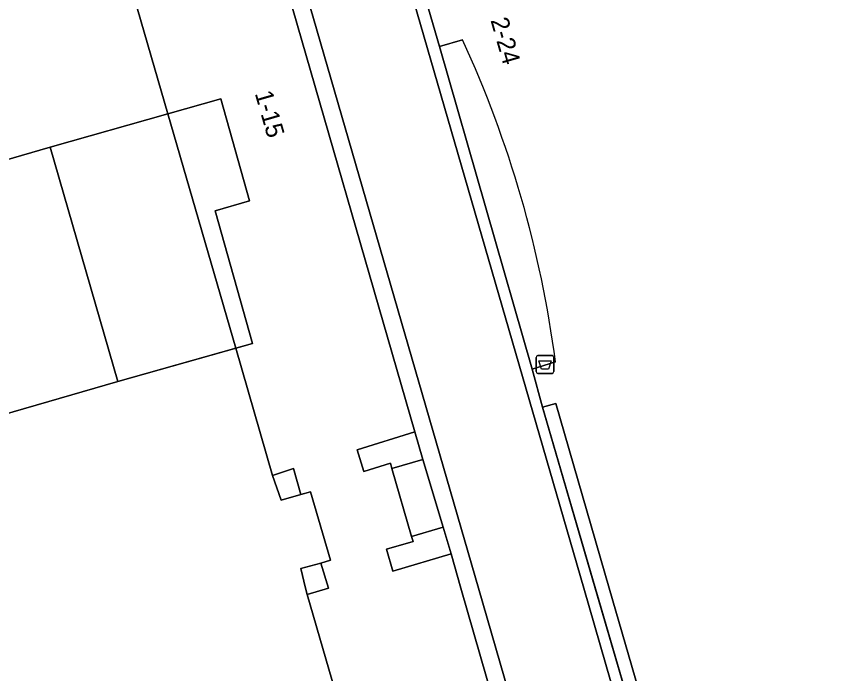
# Model space of a CAD drawing. Extents: x 160806 to 161707, y 383696 to 384148.
# Drawn here: x 161142.86 to 161189.04, y 383745.23 to 383782.03 of the extents above; entities that cross this region are included whole.
import ezdxf

# ---------------------------------------------------------------- set-up
doc = ezdxf.new("R2010")
doc.units = 0
for name, color, linetype in [('IMGEO_Afvalbak', 7, 'Continuous'), ('IMGEO_Muur', 7, 'Continuous'), ('IMGEO_Pand', 7, 'Continuous'), ('IMGEO_Pand_nummerreeks', 7, 'Continuous'), ('IMGEO_Pand_overbouw', 7, 'Continuous'), ('IMGEO_Parkeervlak_gesloten', 7, 'Continuous'), ('IMGEO_Parkeervlak_open', 7, 'Continuous'), ('IMGEO_Rijbaan_lokaal_gesloten', 7, 'Continuous'), ('IMGEO_Voetgangersgebied_open', 7, 'Continuous'), ('IMGEO_Voetpad_op_trap', 7, 'Continuous')]:
    doc.layers.add(name, color=color, linetype=linetype)

msp = doc.modelspace()

# ---------------------------------------------------------------- linework, layer by layer
at = {"layer": 'IMGEO_Afvalbak'}
for p, q in [((161172.084, 383763.034), (161172.874, 383763.034)), ((161172.874, 383763.034), (161172.084, 383763.034)), ((161171.984, 383762.134), (161171.984, 383762.934)), ((161171.984, 383762.934), (161171.984, 383762.134)), ((161172.974, 383762.934), (161172.974, 383762.134)), ((161172.974, 383762.134), (161172.974, 383762.934)), ((161172.874, 383762.034), (161172.084, 383762.034)), ((161172.084, 383762.034), (161172.874, 383762.034))]:
    msp.add_line(p, q, dxfattribs=at)
msp.add_lwpolyline([(161172.127, 383762.748), (161172.831, 383762.748), (161172.682, 383762.278), (161172.276, 383762.278), (161172.127, 383762.748)], dxfattribs=at)
for centre, start, end in [((161172.084, 383762.934), 90, 180), ((161172.084, 383762.934), 90, 180), ((161172.874, 383762.934), 0, 90), ((161172.874, 383762.934), 360, 90), ((161172.084, 383762.134), 180, 270), ((161172.084, 383762.134), 180, 270), ((161172.874, 383762.134), 270, 0), ((161172.874, 383762.134), 270, 0)]:
    msp.add_arc(centre, 0.1, start, end, dxfattribs=at)
at = {"layer": 'IMGEO_Muur'}
for points in [[(161165.635, 383757.209), (161165.188, 383758.759), (161161.944, 383757.756), (161162.319, 383756.541), (161163.812, 383757.001), (161163.896, 383756.713)], [(161157.692, 383754.928), (161158.801, 383755.259), (161158.381, 383756.705), (161157.212, 383756.317)], [(161165.005, 383752.909), (161165.089, 383752.622), (161163.592, 383752.184), (161163.95, 383750.966), (161167.213, 383751.923), (161166.779, 383753.429)], [(161159.142, 383749.659), (161160.337, 383750), (161159.91, 383751.416), (161158.79, 383751.101), (161159.059, 383750)]]:
    msp.add_lwpolyline(points, close=True, dxfattribs=at)
at = {"layer": 'IMGEO_Pand'}
for points in [[(161221.311, 383832.189), (161220.955, 383833.419), (161219.851, 383837.235), (161216.277, 383836.232), (161215.039, 383840.515), (161214.94, 383840.857), (161157.832, 383824.35), (161159.26, 383819.473), (161155.555, 383818.417), (161155.737, 383817.796), (161156.438, 383818.002), (161166.655, 383782.656), (161165.953, 383782.453), (161166.564, 383780.339), (161167.861, 383780.714)], [(161173.066, 383762.677), (161171.77, 383762.265), (161172.335, 383760.149), (161173.08, 383760.356), (161176.084, 383750), (161179.163, 383739.382), (161178.467, 383739.155), (161178.645, 383738.55), (161182.409, 383739.64), (161183.813, 383734.789), (161191.93, 383737.142), (161236.286, 383750), (161240.864, 383751.327), (161239.522, 383755.972), (161243.065, 383757.002), (161221.311, 383832.189)], [(161172.066, 383735.084), (161167.767, 383750), (161167.213, 383751.923), (161163.95, 383750.966), (161163.592, 383752.184), (161165.089, 383752.622), (161165.005, 383752.909), (161163.896, 383756.713), (161163.812, 383757.001), (161162.319, 383756.541), (161161.944, 383757.756), (161165.188, 383758.759), (161157.328, 383786.009)], [(161149.261, 383783.747), (161151.34, 383776.574), (161154.306, 383777.411), (161155.919, 383771.696), (161153.991, 383771.151), (161156.091, 383763.71), (161155.146, 383763.443), (161157.212, 383756.317), (161158.381, 383756.705), (161158.801, 383755.259), (161159.336, 383755.412), (161160.45, 383751.574), (161159.91, 383751.416), (161160.337, 383750), (161159.142, 383749.659), (161161.241, 383742.441)]]:
    msp.add_lwpolyline(points, dxfattribs=at)
msp.add_lwpolyline([(161144.737, 383774.709), (161111.5, 383765.061), (161112.655, 383761.086), (161111.258, 383760.68), (161113.902, 383751.548), (161148.546, 383761.579)], close=True, dxfattribs=at)
msp.add_arc((161110.965, 383754.526), 62.634, 7.47771, 24.71576, dxfattribs=at)
at = {"layer": 'IMGEO_Pand_overbouw'}
for points in [[(161167.861, 383780.714), (161166.564, 383780.339)], [(161166.564, 383780.339), (161171.77, 383762.265), (161173.066, 383762.677)]]:
    msp.add_lwpolyline(points, dxfattribs=at)
for points in [[(161144.737, 383774.709), (161148.546, 383761.579), (161156.091, 383763.71), (161153.991, 383771.151), (161155.919, 383771.696), (161154.306, 383777.411)], [(161172.335, 383760.149), (161178.467, 383739.155), (161179.163, 383739.382), (161176.084, 383750), (161173.08, 383760.356)]]:
    msp.add_lwpolyline(points, close=True, dxfattribs=at)
msp.add_arc((161110.965, 383754.526), 62.634, 7.47771, 24.71576, dxfattribs=at)
at = {"layer": 'IMGEO_Parkeervlak_gesloten'}
msp.add_lwpolyline([(161113.902, 383751.548), (161121.123, 383726.602), (161122.53, 383727.008), (161121.382, 383730.964), (161154.664, 383740.617), (161161.241, 383742.441), (161159.142, 383749.659), (161159.059, 383750), (161158.79, 383751.101), (161159.91, 383751.416), (161160.45, 383751.574), (161159.336, 383755.412), (161158.801, 383755.259), (161157.692, 383754.928), (161157.212, 383756.317), (161155.146, 383763.443), (161148.546, 383761.579)], close=True, dxfattribs=at)
at = {"layer": 'IMGEO_Parkeervlak_open'}
msp.add_lwpolyline([(161104.037, 383785.627), (161111.258, 383760.68), (161112.655, 383761.086), (161111.5, 383765.061), (161144.737, 383774.709), (161151.34, 383776.574), (161149.261, 383783.747), (161149.393, 383783.784), (161148.975, 383785.247), (161150.034, 383785.528), (161150.572, 383785.685), (161149.449, 383789.537), (161148.91, 383789.383), (161147.854, 383789.064), (161147.448, 383790.495), (161147.304, 383790.45), (161145.248, 383797.544), (161138.655, 383795.672)], close=True, dxfattribs=at)
at = {"layer": 'IMGEO_Rijbaan_lokaal_gesloten'}
msp.add_lwpolyline([(161144.737, 383774.709), (161148.546, 383761.579), (161155.146, 383763.443), (161151.34, 383776.574)], close=True, dxfattribs=at)
at = {"layer": 'IMGEO_Voetgangersgebied_open'}
for points in [[(161153.492, 383823.019), (161174.649, 383750), (161178.009, 383738.404), (161178.645, 383738.55), (161178.467, 383739.155), (161175.299, 383750), (161172.335, 383760.149), (161171.77, 383762.265), (161166.564, 383780.339), (161165.953, 383782.453), (161155.737, 383817.796), (161155.555, 383818.417), (161154.142, 383823.222)], [(161177.035, 383738.181), (161178.009, 383738.404), (161174.649, 383750), (161153.492, 383823.019), (161148.092, 383821.328), (161156.16, 383793.469), (161168.744, 383750), (161172.636, 383736.558), (161173.934, 383732.031), (161178.418, 383733.322)], [(161147.904, 383818.638), (161155.337, 383792.863), (161155.777, 383791.339), (161156.886, 383787.54), (161157.328, 383786.009), (161165.188, 383758.759), (161165.635, 383757.209), (161166.779, 383753.429), (161167.213, 383751.923), (161167.767, 383750), (161172.066, 383735.084), (161172.961, 383731.747), (161173.934, 383732.031), (161172.636, 383736.558), (161168.744, 383750), (161156.16, 383793.469), (161148.092, 383821.328), (161147.266, 383821.092)], [(161172.335, 383760.149), (161175.299, 383750), (161178.467, 383739.155), (161179.163, 383739.382), (161176.084, 383750), (161173.08, 383760.356)]]:
    msp.add_lwpolyline(points, close=True, dxfattribs=at)
msp.add_lwpolyline([(161167.861, 383780.714), (161166.564, 383780.339), (161171.77, 383762.265), (161173.066, 383762.677)], dxfattribs=at)
msp.add_arc((161110.965, 383754.526), 62.634, 7.47771, 24.71576, dxfattribs=at)
at = {"layer": 'IMGEO_Voetpad_op_trap'}
for points in [[(161156.091, 383763.71), (161153.991, 383771.151), (161155.919, 383771.696), (161154.306, 383777.411), (161151.34, 383776.574), (161155.146, 383763.443)], [(161163.896, 383756.713), (161165.005, 383752.909), (161166.779, 383753.429), (161165.635, 383757.209)]]:
    msp.add_lwpolyline(points, close=True, dxfattribs=at)

# ---------------------------------------------------------------- texts
at = {"layer": 'IMGEO_Pand_nummerreeks'}
for s, rotation, p in [('2-24', 286.1228, (161169.418, 383781.821)), ('1-15', 286.1443, (161156.206, 383777.724))]:
    msp.add_text(s, height=1, rotation=rotation, dxfattribs=at).set_placement(p)

doc.saveas('drawing.dxf')
